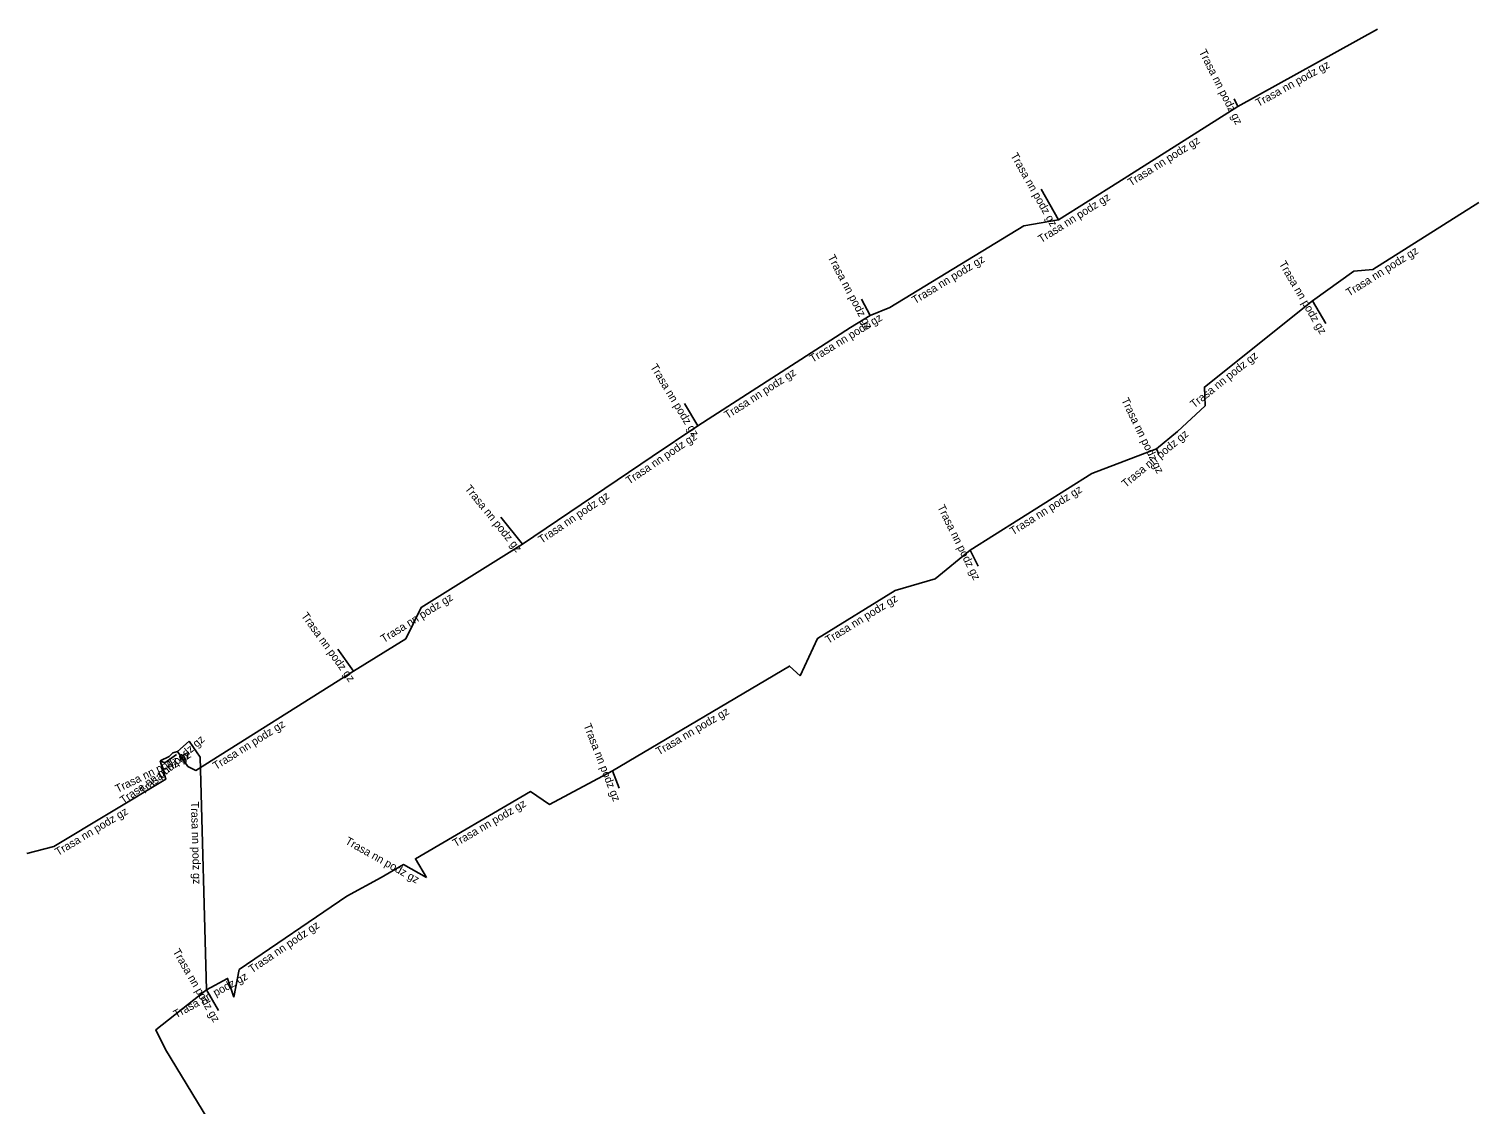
# Model space of a CAD drawing. Extents: x -467803 to -467116, y -1117596 to -1116713.
# Drawn here: x -467477.4 to -467386.8, y -1116866.1 to -1116798.8 of the extents above; entities that cross this region are included whole.
import ezdxf

# ---------------------------------------------------------------- set-up
doc = ezdxf.new("R2010")
doc.units = 0
doc.layers.add('Popiskový text - Ostatní atributy Trasy', color=7, linetype='Continuous')
doc.layers.add('Spojnice NN', color=7, linetype='Continuous')

msp = doc.modelspace()

# ---------------------------------------------------------------- linework, layer by layer
at = {"layer": 'Spojnice NN'}
for points in [[(-467393.143, -1116798.839), (-467401.873, -1116803.68)], [(-467401.873, -1116803.68), (-467409.37, -1116808.426)], [(-467401.873, -1116803.68), (-467402.11, -1116803.21)], [(-467413.076, -1116810.772), (-467414.158, -1116808.855)], [(-467409.37, -1116808.426), (-467413.076, -1116810.772)], [(-467386.81, -1116809.69), (-467393.45, -1116813.87), (-467394.63, -1116813.98), (-467397.22, -1116815.83)], [(-467413.076, -1116810.772), (-467415.26, -1116811.136), (-467423.62, -1116816.24), (-467424.86, -1116816.74)], [(-467424.86, -1116816.74), (-467425.397, -1116815.726)], [(-467397.22, -1116815.83), (-467403.97, -1116821.21), (-467403.92, -1116822.38), (-467405.65, -1116823.98)], [(-467397.22, -1116815.83), (-467396.39, -1116817.25)], [(-467424.86, -1116816.74), (-467426.084, -1116817.491)], [(-467426.084, -1116817.491), (-467435.622, -1116823.638)], [(-467435.622, -1116823.638), (-467436.462, -1116822.249)], [(-467435.622, -1116823.638), (-467438.467, -1116825.559)], [(-467405.65, -1116823.98), (-467406.97, -1116825.08)], [(-467438.467, -1116825.559), (-467446.567, -1116831.028)], [(-467406.97, -1116825.08), (-467411.01, -1116826.62), (-467418.61, -1116831.4)], [(-467406.97, -1116825.08), (-467406.81, -1116825.41)], [(-467446.567, -1116831.028), (-467447.935, -1116829.345)], [(-467446.567, -1116831.028), (-467452.901, -1116834.979), (-467453.876, -1116836.942), (-467457.128, -1116838.966)], [(-467418.61, -1116831.4), (-467420.8, -1116833.2), (-467423.3, -1116833.92), (-467428.14, -1116836.92), (-467429.22, -1116839.25)], [(-467418.61, -1116831.4), (-467418.11, -1116832.41)], [(-467457.128, -1116838.966), (-467458.118, -1116837.598)], [(-467457.128, -1116838.966), (-467466.986, -1116845.166), (-467467.486, -1116844.927), (-467468.14, -1116843.973)], [(-467429.22, -1116839.25), (-467429.89, -1116838.65), (-467440.96, -1116845.2)], [(-467468.14, -1116843.973), (-467467.415, -1116843.329)], [(-467467.415, -1116843.329), (-467466.725, -1116844.334), (-467466.32, -1116858.88)], [(-467469.226, -1116844.561), (-467468.873, -1116845.712), (-467475.868, -1116849.925), (-467477.555, -1116850.353)], [(-467468.14, -1116843.973), (-467468.417, -1116844.062), (-467468.66, -1116844.286), (-467469.226, -1116844.561)], [(-467469.226, -1116844.561), (-467468.928, -1116844.686), (-467468.206, -1116844.18)], [(-467440.96, -1116845.2), (-467444.89, -1116847.29), (-467446.08, -1116846.49), (-467453.27, -1116850.68), (-467452.57, -1116851.86)], [(-467440.96, -1116845.2), (-467440.54, -1116846.27)], [(-467455.402, -1116851.852), (-467457.55, -1116853.03), (-467464.28, -1116857.61), (-467464.62, -1116859.34)], [(-467452.57, -1116851.86), (-467454.01, -1116851.05), (-467455.402, -1116851.852)], [(-467464.62, -1116859.34), (-467465.01, -1116858.16), (-467466.32, -1116858.88)], [(-467466.32, -1116858.88), (-467469.49, -1116861.38), (-467468.89, -1116862.61), (-467464.24, -1116870.24), (-467459.39, -1116877.46), (-467449.59, -1116892.71)], [(-467466.32, -1116858.88), (-467465.574, -1116860.176)]]:
    msp.add_lwpolyline(points, dxfattribs=at)

# ---------------------------------------------------------------- texts
at = {"layer": 'Popiskový text - Ostatní atributy Trasy'}
for rotation, p in [(296.75977, (-467404.325, -1116800.261)), (29.00945, (-467400.598, -1116803.716)), (32.33599, (-467408.564, -1116808.685)), (299.44141, (-467416.097, -1116806.742)), (32.33494, (-467414.165, -1116812.231)), (297.90506, (-467427.525, -1116813.096)), (32.19116, (-467394.927, -1116815.568)), (31.40516, (-467422.05, -1116816.043)), (300.30659, (-467399.331, -1116813.507)), (31.5317, (-467428.451, -1116819.705)), (38.55614, (-467404.614, -1116822.554)), (301.16352, (-467438.613, -1116819.948)), (32.80076, (-467433.773, -1116823.22)), (295.86636, (-467409.174, -1116822.025)), (34.028, (-467439.908, -1116827.316)), (39.80557, (-467408.885, -1116827.522)), (309.10539, (-467450.211, -1116827.575)), (32.16773, (-467415.93, -1116830.483)), (34.02664, (-467445.38, -1116831.011)), (296.33769, (-467420.67, -1116828.703)), (31.95494, (-467455.248, -1116837.21)), (31.79207, (-467427.468, -1116837.268)), (305.89267, (-467460.432, -1116835.509)), (30.61235, (-467438.058, -1116844.238)), (32.16705, (-467465.731, -1116845.145)), (291.43117, (-467442.777, -1116842.348)), (41.6041, (-467470.258, -1116846.722)), (25.91353, (-467471.882, -1116846.573)), (35.02396, (-467471.515, -1116847.292)), (271.59491, (-467467.297, -1116847.124)), (30.23166, (-467450.762, -1116849.97)), (31.06002, (-467475.6, -1116850.523)), (330.64225, (-467457.702, -1116849.719)), (34.23665, (-467463.484, -1116857.855)), (299.92547, (-467468.453, -1116856.478)), (28.794, (-467468.22, -1116860.666))]:
    msp.add_text('Trasa nn podz gz', height=0.5, rotation=rotation, dxfattribs=at).set_placement(p)

doc.saveas('drawing.dxf')
